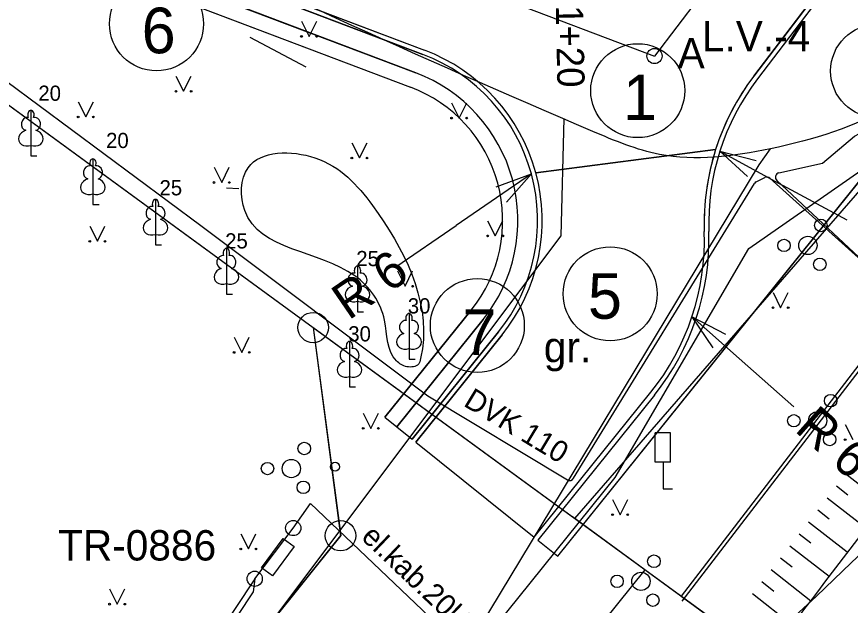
# Model space of a CAD drawing. Extents: x 514086 to 514457, y 297399 to 297567.
# Drawn here: x 514219.51 to 514246.93, y 297411.35 to 297430.72 of the extents above; entities that cross this region are included whole.
import ezdxf

# ---------------------------------------------------------------- set-up
doc = ezdxf.new("R2010")
doc.units = 0
for name, color, linetype in [('AA_Apzimejumi', 7, 'Continuous'), ('AA_Brauktuve', 7, 'Continuous'), ('AA_cela_mala', 7, 'Continuous'), ('AA_grants', 7, 'Continuous'), ('AA_Ielas_ass', 7, 'Continuous'), ('AA_izmeri', 7, 'Continuous'), ('AA_Nomale', 7, 'Continuous'), ('AA_Zale', 7, 'Continuous'), ('Level 1', 7, 'Continuous'), ('Level 14', 7, 'Continuous'), ('Level 16', 7, 'Continuous'), ('Level 18', 7, 'Continuous'), ('Level 23', 7, 'Continuous'), ('Level 29', 7, 'Continuous'), ('Level 31', 7, 'Continuous'), ('Level 32', 7, 'Continuous'), ('Level 35', 7, 'Continuous'), ('Level 36', 7, 'Continuous'), ('Level 37', 7, 'Continuous'), ('Level 42', 7, 'Continuous'), ('Level 45', 7, 'Continuous'), ('Level 46', 7, 'Continuous'), ('Level 61', 7, 'Continuous'), ('Level 7', 7, 'Continuous')]:
    doc.layers.add(name, color=color, linetype=linetype)

msp = doc.modelspace()

# ---------------------------------------------------------------- linework, layer by layer
at = {"layer": 'AA_Apzimejumi'}
for centre in [(514224.106, 297430.487), (514247.83, 297428.935), (514239.938, 297428.287), (514239.03, 297421.6), (514234.661, 297420.557)]:
    msp.add_circle(centre, 1.546, dxfattribs=at)
at = {"layer": 'AA_Brauktuve'}
msp.add_line((514236.585, 297425.586), (514242.499, 297426.346), dxfattribs=at)
for points in [[(514211.866, 297437.597), (514214.554, 297436.578), (514232.921, 297429.621)], [(514243.754, 297428.764), (514246.598, 297432.504)], [(514236.585, 297425.586), (514242.499, 297426.346)]]:
    msp.add_lwpolyline(points, dxfattribs=at)
for centre, radius, start, end in [((514230.796, 297424.01), 6, 15.2367, 69.2528), ((514250.123, 297423.922), 8, 142.7529, 162.3604)]:
    msp.add_arc(centre, radius, start, end, dxfattribs=at)
at = {"layer": 'AA_cela_mala'}
for p, q in [((514214.501, 297436.438), (514232.868, 297429.48)), ((514214.554, 297436.578), (514232.921, 297429.621)), ((514246.598, 297432.504), (514243.754, 297428.764)), ((514246.718, 297432.413), (514243.874, 297428.673)), ((514235.356, 297420.346), (514232.52, 297416.815)), ((514232.637, 297416.721), (514235.473, 297420.252)), ((514236.535, 297413.59), (514240.369, 297418.362)), ((514240.486, 297418.268), (514236.652, 297413.496)), ((514232.637, 297416.721), (514236.535, 297413.59))]:
    msp.add_line(p, q, dxfattribs=at)
for centre, radius, start, end in [((514230.796, 297424.01), 5.85, 321.2206, 69.2528), ((514230.796, 297424.01), 6, 321.2206, 69.2528), ((514250.123, 297423.922), 8, 142.7529, 181.9678), ((514250.123, 297423.922), 7.85, 142.7529, 181.9678), ((514234.132, 297423.372), 8, 321.2208, 1.9678), ((514234.132, 297423.372), 8.15, 321.2208, 1.9678)]:
    msp.add_arc(centre, radius, start, end, dxfattribs=at)
at = {"layer": 'AA_grants'}
for points in [[(514242.499, 297426.346), (514236.585, 297425.586)], [(514235.473, 297420.252), (514232.637, 297416.721), (514236.535, 297413.59), (514240.369, 297418.362)]]:
    msp.add_lwpolyline(points, dxfattribs=at)
for centre, radius, start, end in [((514250.123, 297423.922), 8, 162.3604, 181.9678), ((514230.796, 297424.01), 6, 321.2206, 15.2367), ((514234.132, 297423.372), 8, 321.2208, 1.9678)]:
    msp.add_arc(centre, radius, start, end, dxfattribs=at)
at = {"layer": 'AA_Ielas_ass'}
for p in [(514245.01, 297435.371), (514233.507, 297432.072)]:
    msp.add_line(p, (514240.49, 297429.427), dxfattribs=at)
msp.add_circle((514240.49, 297429.427), 0.25, dxfattribs=at)
at = {"layer": 'AA_izmeri'}
for p, q in [((514242.642, 297426.301), (514244.715, 297425.17)), ((514236.44, 297425.547), (514233.96, 297423.85)), ((514246.822, 297424.02), (514244.715, 297425.17)), ((514231.979, 297422.494), (514233.96, 297423.85)), ((514241.723, 297420.846), (514243.277, 297419.471)), ((514245.075, 297417.881), (514243.277, 297419.471))]:
    msp.add_line(p, q, dxfattribs=at)
for points in [[(514243.552, 297425.462), (514242.642, 297426.301), (514243.839, 297425.989)], [(514235.28, 297425.117), (514236.44, 297425.547), (514235.619, 297424.622)], [(514242.423, 297419.827), (514241.723, 297420.846), (514242.82, 297420.276)]]:
    msp.add_lwpolyline(points, dxfattribs=at)
at = {"layer": 'AA_Nomale'}
for points in [[(514213.882, 297436.432), (514214.457, 297435.759), (514232.638, 297428.872)], [(514232.868, 297429.48), (514214.501, 297436.438)], [(514234.85, 297420.753), (514232.013, 297417.222), (514232.52, 297416.815), (514235.356, 297420.346)]]:
    msp.add_lwpolyline(points, dxfattribs=at)
for radius in [5.85, 5.2]:
    msp.add_arc((514230.796, 297424.01), radius, 321.2206, 69.2528, dxfattribs=at)
at = {"layer": 'AA_Zale'}
for p, q in [((514214.457, 297435.759), (514232.638, 297428.872)), ((514213.813, 297435.469), (514232.461, 297428.405)), ((514237.314, 297412.963), (514250.581, 297429.476)), ((514231.623, 297417.536), (514234.46, 297421.066)), ((514232.013, 297417.222), (514234.85, 297420.753)), ((514231.623, 297417.536), (514232.013, 297417.222)), ((514232.013, 297417.222), (514232.52, 297416.815)), ((514236.652, 297413.496), (514237.314, 297412.963))]:
    msp.add_line(p, q, dxfattribs=at)
for points in [[(514236.652, 297413.496), (514237.314, 297412.963), (514250.581, 297429.476), (514253.4, 297427.333), (514283.198, 297466.177), (514325.029, 297520.708), (514327.112, 297523.423), (514336.853, 297525.444), (514334.256, 297529.664)], [(514232.638, 297428.872), (514214.457, 297435.759), (514213.813, 297435.469), (514232.461, 297428.405)], [(514246.718, 297432.413), (514243.874, 297428.673)], [(514234.46, 297421.066), (514231.623, 297417.536)], [(514231.623, 297417.536), (514232.013, 297417.222), (514234.85, 297420.753)], [(514240.486, 297418.268), (514236.652, 297413.496)]]:
    msp.add_lwpolyline(points, dxfattribs=at)
for centre, radius, start, end in [((514230.796, 297424.01), 5.2, 321.2206, 69.2528), ((514230.796, 297424.01), 5.2, 321.2206, 69.2528), ((514250.123, 297423.922), 7.85, 142.7529, 181.9678), ((514230.796, 297424.01), 4.7, 321.2206, 69.2528), ((514230.796, 297424.01), 4.7, 321.2206, 69.2528), ((514234.132, 297423.372), 8.15, 321.2208, 1.9678)]:
    msp.add_arc(centre, radius, start, end, dxfattribs=at)
at = {"layer": 'Level 1'}
for p, q in [((514219.975, 297426.486), (514219.975, 297426.139)), ((514219.975, 297426.139), (514220.175, 297426.139)), ((514222.015, 297424.888), (514222.015, 297424.541)), ((514222.015, 297424.541), (514222.215, 297424.541)), ((514224.074, 297423.557), (514224.074, 297423.21)), ((514224.074, 297423.21), (514224.274, 297423.21)), ((514226.405, 297421.94), (514226.405, 297421.593)), ((514226.405, 297421.593), (514226.605, 297421.593)), ((514230.718, 297421.359), (514230.718, 297421.012)), ((514230.718, 297421.012), (514230.918, 297421.012)), ((514232.413, 297419.802), (514232.413, 297419.455)), ((514232.413, 297419.455), (514232.613, 297419.455)), ((514230.455, 297418.882), (514230.455, 297418.535)), ((514230.455, 297418.535), (514230.655, 297418.535))]:
    msp.add_line(p, q, dxfattribs=at)
for points in [[(514219.975, 297427.639), (514219.975, 297426.486)], [(514220.064, 297427.407), (514220.063, 297427.408)], [(514222.015, 297426.041), (514222.015, 297424.888)], [(514222.105, 297425.809), (514222.104, 297425.81)], [(514224.074, 297424.71), (514224.074, 297423.557)], [(514224.163, 297424.477), (514224.162, 297424.478)], [(514226.405, 297423.093), (514226.405, 297421.94)], [(514226.495, 297422.861), (514226.494, 297422.862)], [(514230.718, 297422.512), (514230.718, 297421.359)], [(514230.808, 297422.28), (514230.807, 297422.281)], [(514232.413, 297420.955), (514232.413, 297419.802)], [(514232.503, 297420.723), (514232.502, 297420.724)], [(514230.455, 297420.035), (514230.455, 297418.882)], [(514230.545, 297419.803), (514230.544, 297419.804)]]:
    msp.add_lwpolyline(points, dxfattribs=at)
for centre, radius in [((514245.961, 297423.853), 0.207), ((514245.534, 297423.193), 0.301), ((514244.75, 297423.193), 0.204), ((514245.929, 297422.573), 0.205), ((514246.284, 297418.084), 0.207), ((514245.857, 297417.424), 0.301), ((514245.073, 297417.424), 0.204), ((514246.252, 297416.804), 0.205), ((514228.968, 297416.51), 0.207), ((514227.757, 297415.85), 0.204), ((514228.541, 297415.85), 0.301), ((514228.936, 297415.23), 0.205), ((514240.469, 297412.799), 0.207), ((514239.258, 297412.139), 0.204), ((514240.042, 297412.139), 0.301), ((514240.437, 297411.519), 0.205)]:
    msp.add_circle(centre, radius, dxfattribs=at)
for centre, major_axis, ratio, start_param, end_param in [((514219.975, 297427.489), (0, -0.15), 0.707107, 3.14537, 5.287485), ((514219.974, 297427.489), (0, -0.15), 0.707107, 0.995701, 3.137816), ((514219.846, 297427.194), (-0.039, -0.212), 0.861323, 3.141593, 6.283185), ((514220.103, 297427.194), (0.039, -0.212), 0.861323, 0, 3.141593), ((514219.885, 297426.732), (0.307, 0.095), 0.814445, 1.570796, 4.752015), ((514220.064, 297426.732), (-0.307, 0.095), 0.814445, 1.531171, 4.712389), ((514222.016, 297425.891), (0, -0.15), 0.707107, 3.14537, 5.287485), ((514222.015, 297425.891), (0, -0.15), 0.707107, 0.995701, 3.137816), ((514221.887, 297425.597), (-0.039, -0.212), 0.861323, 3.141593, 6.283185), ((514222.144, 297425.597), (0.039, -0.212), 0.861323, 0, 3.141593), ((514221.926, 297425.134), (0.307, 0.095), 0.814445, 1.570796, 4.752015), ((514222.105, 297425.134), (-0.307, 0.095), 0.814445, 1.531171, 4.712389), ((514224.074, 297424.56), (0, -0.15), 0.707107, 3.14537, 5.287485), ((514224.073, 297424.56), (0, -0.15), 0.707107, 0.995701, 3.137816), ((514223.945, 297424.265), (-0.039, -0.212), 0.861323, 3.141593, 6.283185), ((514224.202, 297424.265), (0.039, -0.212), 0.861323, 0, 3.141593), ((514223.984, 297423.803), (0.307, 0.095), 0.814445, 1.570796, 4.752015), ((514224.163, 297423.803), (-0.307, 0.095), 0.814445, 1.531171, 4.712389), ((514226.277, 297422.648), (-0.039, -0.212), 0.861323, 3.141593, 6.283185), ((514226.405, 297422.943), (0, -0.15), 0.707107, 3.14537, 5.287485), ((514226.405, 297422.943), (0, -0.15), 0.707107, 0.995701, 3.137816), ((514226.533, 297422.648), (0.039, -0.212), 0.861323, 0, 3.141593), ((514226.315, 297422.186), (0.307, 0.095), 0.814445, 1.570796, 4.752015), ((514226.495, 297422.186), (-0.307, 0.095), 0.814445, 1.531171, 4.712389), ((514230.718, 297422.362), (0, -0.15), 0.707107, 3.14537, 5.287485), ((514230.718, 297422.362), (0, -0.15), 0.707107, 0.995701, 3.137816), ((514230.59, 297422.067), (-0.039, -0.212), 0.861323, 3.141593, 6.283185), ((514230.846, 297422.067), (0.039, -0.212), 0.861323, 0, 3.141593), ((514230.628, 297421.605), (0.307, 0.095), 0.814445, 1.570796, 4.752015), ((514230.808, 297421.605), (-0.307, 0.095), 0.814445, 1.531171, 4.712389), ((514232.413, 297420.805), (0, -0.15), 0.707107, 3.14537, 5.287485), ((514232.413, 297420.805), (0, -0.15), 0.707107, 0.995701, 3.137816), ((514232.285, 297420.51), (-0.039, -0.212), 0.861323, 3.141593, 6.283185), ((514232.541, 297420.51), (0.039, -0.212), 0.861323, 0, 3.141593), ((514232.323, 297420.048), (0.307, 0.095), 0.814445, 1.570796, 4.752015), ((514232.503, 297420.048), (-0.307, 0.095), 0.814445, 1.531171, 4.712389), ((514230.455, 297419.885), (0, -0.15), 0.707107, 3.14537, 5.287485), ((514230.455, 297419.885), (0, -0.15), 0.707107, 0.995701, 3.137816), ((514230.327, 297419.59), (-0.039, -0.212), 0.861323, 3.141593, 6.283185), ((514230.583, 297419.59), (0.039, -0.212), 0.861323, 0, 3.141593), ((514230.365, 297419.128), (0.307, 0.095), 0.814445, 1.570796, 4.752015), ((514230.545, 297419.128), (-0.307, 0.095), 0.814445, 1.531171, 4.712389)]:
    msp.add_ellipse(centre, major_axis=major_axis, ratio=ratio, start_param=start_param, end_param=end_param, dxfattribs=at)
at = {"layer": 'Level 14'}
msp.add_circle((514229.982, 297415.908), 0.148, dxfattribs=at)
at = {"layer": 'Level 16'}
for p, q in [((514241.016, 297417.027), (514240.516, 297417.027)), ((514240.516, 297416.058), (514240.516, 297417.027)), ((514241.016, 297416.058), (514241.016, 297417.027)), ((514241.016, 297416.058), (514240.516, 297416.058)), ((514240.77, 297416.058), (514240.77, 297415.18)), ((514240.77, 297415.18), (514241.085, 297415.18))]:
    msp.add_line(p, q, dxfattribs=at)
at = {"layer": 'Level 18'}
msp.add_line((514227.337, 297412.224), (514228.605, 297413.892), dxfattribs=at)
msp.add_lwpolyline([(514227.561, 297412.586), (514228.272, 297413.553), (514228.635, 297413.286), (514227.924, 297412.319)], close=True, dxfattribs=at)
for centre in [(514228.605, 297413.892), (514227.337, 297412.224)]:
    msp.add_circle(centre, 0.25, dxfattribs=at)
at = {"layer": 'Level 23'}
for p, q in [((514228.877, 297430.571), (514229.127, 297430.071)), ((514229.127, 297430.071), (514229.377, 297430.571)), ((514224.747, 297428.766), (514224.997, 297428.266)), ((514224.997, 297428.266), (514225.247, 297428.766)), ((514221.53, 297427.922), (514221.78, 297427.422)), ((514221.78, 297427.422), (514222.03, 297427.922)), ((514233.812, 297427.883), (514234.062, 297427.383)), ((514234.062, 297427.383), (514234.312, 297427.883)), ((514230.533, 297426.571), (514230.783, 297426.071)), ((514230.783, 297426.071), (514231.033, 297426.571)), ((514226.001, 297425.765), (514226.251, 297425.265)), ((514226.251, 297425.265), (514226.501, 297425.765)), ((514234.999, 297424.008), (514235.249, 297423.508)), ((514235.249, 297423.508), (514235.499, 297424.008)), ((514221.912, 297423.829), (514222.162, 297423.329)), ((514222.162, 297423.329), (514222.412, 297423.829)), ((514232.032, 297422.352), (514232.282, 297421.852)), ((514232.282, 297421.852), (514232.532, 297422.352)), ((514244.388, 297421.645), (514244.638, 297421.145)), ((514244.638, 297421.145), (514244.888, 297421.645)), ((514226.66, 297420.172), (514226.91, 297419.672)), ((514226.91, 297419.672), (514227.16, 297420.172)), ((514230.908, 297417.672), (514231.158, 297417.172)), ((514231.158, 297417.172), (514231.408, 297417.672)), ((514246.762, 297417.301), (514247.012, 297416.801)), ((514239.11, 297414.832), (514239.36, 297414.332)), ((514239.36, 297414.332), (514239.61, 297414.832)), ((514226.878, 297413.703), (514227.128, 297413.203)), ((514227.128, 297413.203), (514227.378, 297413.703)), ((514222.563, 297411.887), (514222.813, 297411.387)), ((514222.813, 297411.387), (514223.063, 297411.887))]:
    msp.add_line(p, q, dxfattribs=at)
for centre, radius in [((514228.877, 297430.071), 0.028), ((514229.377, 297430.071), 0.0263), ((514224.746, 297428.266), 0.028), ((514225.246, 297428.266), 0.0263), ((514221.529, 297427.422), 0.028), ((514222.029, 297427.422), 0.0263), ((514233.812, 297427.383), 0.028), ((514234.312, 297427.383), 0.0263), ((514230.532, 297426.07), 0.028), ((514231.032, 297426.07), 0.0263), ((514226, 297425.265), 0.028), ((514226.5, 297425.265), 0.0263), ((514234.999, 297423.508), 0.028), ((514235.499, 297423.508), 0.0263), ((514221.912, 297423.328), 0.028), ((514222.412, 297423.328), 0.0263), ((514232.032, 297421.851), 0.028), ((514232.532, 297421.851), 0.0263), ((514244.388, 297421.145), 0.028), ((514244.888, 297421.145), 0.0263), ((514226.66, 297419.672), 0.028), ((514227.16, 297419.672), 0.0263), ((514230.907, 297417.172), 0.028), ((514231.407, 297417.172), 0.0263), ((514246.762, 297416.801), 0.028), ((514239.109, 297414.332), 0.028), ((514239.609, 297414.332), 0.0263), ((514226.878, 297413.203), 0.028), ((514227.378, 297413.203), 0.0263), ((514222.563, 297411.387), 0.028), ((514223.063, 297411.387), 0.0263)]:
    msp.add_circle(centre, radius, dxfattribs=at)
at = {"layer": 'Level 29'}
for p, q in [((514325.029, 297520.708), (514241.366, 297411.646)), ((514139.134, 297486.37), (514229.261, 297420.493)), ((514229.248, 297420.503), (514241.354, 297411.656)), ((514229.261, 297420.493), (514230.166, 297413.646)), ((514220.185, 297401.223), (514230.166, 297413.646)), ((514241.366, 297411.646), (514242.591, 297410.75))]:
    msp.add_line(p, q, dxfattribs=at)
at = {"layer": 'Level 31'}
for p, q in [((514246.779, 297415.68), (514248.041, 297414.698)), ((514246.472, 297415.285), (514246.851, 297414.99)), ((514246.165, 297414.891), (514247.43, 297413.906)), ((514245.857, 297414.496), (514246.239, 297414.199)), ((514245.55, 297414.101), (514246.83, 297413.106)), ((514245.243, 297413.707), (514245.629, 297413.406)), ((514244.936, 297413.312), (514246.23, 297412.306)), ((514244.629, 297412.917), (514245.02, 297412.613)), ((514244.322, 297412.523), (514245.635, 297411.502)), ((514244.015, 297412.128), (514244.412, 297411.819)), ((514243.708, 297411.733), (514245.041, 297410.697))]:
    msp.add_line(p, q, dxfattribs=at)
msp.add_spline([(514238.182, 297404.63), (514268.566, 297443.685), (514271.22, 297450.146), (514276.219, 297454.734), (514284.527, 297466.568), (514290.967, 297471.565), (514316.058, 297506.3)], degree=3, dxfattribs=at)
at = {"layer": 'Level 32'}
msp.add_line((514226.811, 297425.06), (514226.412, 297425.083), dxfattribs=at)
msp.add_spline([(514232.773, 297419.368), (514232.852, 297419.791), (514231.214, 297424.503), (514229.318, 297426.076), (514227.122, 297425.752), (514227.007, 297424.341), (514230.636, 297422.19), (514231.607, 297420.733), (514232, 297419.391), (514232.341, 297419.202), (514232.56, 297419.202), (514232.72, 297419.277), (514232.773, 297419.368)], degree=3, dxfattribs=at)
at = {"layer": 'Level 35'}
msp.add_line((514255.58, 297429.98), (514241.388, 297411.486), dxfattribs=at)
at = {"layer": 'Level 36'}
msp.add_spline([(514320.804, 297502.52), (514306.724, 297488.103), (514301.133, 297479.973), (514270.315, 297441.123), (514246.087, 297412.115), (514239.566, 297403.275)], degree=3, dxfattribs=at)
at = {"layer": 'Level 37'}
msp.add_line((514243.929, 297425.848), (514244.303, 297426.375), dxfattribs=at)
for points in [[(514237.507, 297427.371), (514237.405, 297423.511), (514227.557, 297410.382), (514220.597, 297401.223)], [(514228.516, 297401.223), (514234.052, 297409.474), (514243.929, 297425.848)]]:
    msp.add_lwpolyline(points, dxfattribs=at)
msp.add_spline([(514253.266, 297433.337), (514251.138, 297430.251), (514248.312, 297427.806), (514244.303, 297426.375), (514240.654, 297426.189), (514238.461, 297426.944), (514221.666, 297434.465), (514216.865, 297436.605), (514214.873, 297437.26), (514213.856, 297437.22), (514212.841, 297436.761), (514210.686, 297435.157)], degree=3, dxfattribs=at)
at = {"layer": 'Level 42'}
msp.add_line((514227.181, 297430.044), (514229.017, 297429.067), dxfattribs=at)
at = {"layer": 'Level 45'}
msp.add_line((514233.037, 297418.247), (514237.623, 297415.479), dxfattribs=at)
for points in [[(514244.583, 297425.582), (514246.018, 297425.897), (514247.064, 297426.784), (514250.354, 297428.549), (514251.967, 297430.455), (514256.157, 297436.259), (514261.4, 297444.303), (514263.602, 297446.189), (514265.306, 297447.481)], [(514213.849, 297432.553), (514225.562, 297423.85), (514233.037, 297418.247), (514237.623, 297415.479)], [(514243.835, 297425.283), (514244.115, 297425.425)], [(514244.283, 297425.403), (514248.057, 297422.015), (514244.513, 297425.326)], [(514237.829, 297415.529), (514243.775, 297425.228)]]:
    msp.add_lwpolyline(points, dxfattribs=at)
for centre, start, end in [((514244.183, 297425.292), 48.0793, 116.8806), ((514244.615, 297425.436), 102.373, 226.9487), ((514243.903, 297425.149), 116.8806, 148.4892), ((514237.701, 297415.607), 238.8881, 328.4892)]:
    msp.add_arc(centre, 0.15, start, end, dxfattribs=at)
at = {"layer": 'Level 46'}
for p, q in [((514229.26, 297420.49), (514230.16, 297413.64)), ((514230.16, 297413.64), (514220.185, 297401.223))]:
    msp.add_line(p, q, dxfattribs=at)
msp.add_lwpolyline([(514139.134, 297486.37), (514229.261, 297420.493), (514237.863, 297414.208), (514250.009, 297428.181), (514295.433, 297494.723), (514312.775, 297524.542), (514316.491, 297528.738), (514320.446, 297531.016), (514328.236, 297532.215), (514332.539, 297530.572), (514332.631, 297530.536), (514341.642, 297542.18), (514320.211, 297553.997), (514285.885, 297496.27), (514243.195, 297433.696), (514241.534, 297432.407), (514239.451, 297432.203), (514209.969, 297445.237), (514194.45, 297457.413), (514175.859, 297473.677), (514139.316, 297503.122), (514133.046, 297508.174), (514130.604, 297489.221)], close=True, dxfattribs=at)
for points in [[(514229.261, 297420.493), (514230.166, 297413.646), (514220.185, 297401.223)], [(514240.166, 297412.522), (514237.788, 297414.26)], [(514234.937, 297401.223), (514242.591, 297410.75), (514240.166, 297412.522), (514231.088, 297401.223)]]:
    msp.add_lwpolyline(points, dxfattribs=at)
for centre in [(514229.26, 297420.49), (514230.16, 297413.64)]:
    msp.add_circle(centre, 0.5, dxfattribs=at)
at = {"layer": 'Level 61'}
msp.add_lwpolyline([(514228.605, 297413.892), (514229.168, 297414.699), (514234.462, 297409.66), (514239.192, 297415.557), (514243.591, 297423.09), (514250.856, 297428.146), (514250.871, 297429.329), (514257.62, 297437.772), (514268.028, 297450.791), (514271.687, 297455.368), (514283.043, 297472.127), (514296.63, 297489.788), (514299.744, 297491.72), (514308.223, 297503.049), (514310.505, 297506.097), (514314.057, 297510.598), (514322.921, 297521.831), (514325.028, 297524.077), (514326.601, 297524.074), (514327.377, 297523.947), (514343.661, 297512.323), (514343.876, 297512.066)], dxfattribs=at)
at = {"layer": 'Level 7'}
for points in [[(514227.337, 297412.224), (514220.053, 297401.223)], [(514227.337, 297412.224), (514227.292, 297411.794), (514220.292, 297401.223)]]:
    msp.add_lwpolyline(points, dxfattribs=at)

# ---------------------------------------------------------------- texts
at = {"layer": 'AA_Apzimejumi'}
for s, p in [('6', (514223.62, 297429.518)), ('1', (514239.452, 297427.318)), ('5', (514238.301, 297420.779)), ('7', (514234.175, 297419.588))]:
    msp.add_text(s, height=1.5, dxfattribs=at).set_placement(p)
at = {"layer": 'AA_Ielas_ass'}
for s, height, rotation, p in [(' 1+20', 0.9, 271.1307, (514237.235, 297431.426)), ('L.V.-4', 1, 360, (514242.048, 297429.584))]:
    msp.add_text(s, height=height, rotation=rotation, dxfattribs=at).set_placement(p)
at = {"layer": 'AA_izmeri'}
for rotation, p in [(34.3868, (514230.425, 297420.713)), (318.5074, (514245.066, 297417.098))]:
    msp.add_text('R 6', height=1.2, rotation=rotation, dxfattribs=at).set_placement(p)
at = {"layer": 'Level 1'}
for s, p in [('20', (514220.22, 297427.953)), ('20', (514222.448, 297426.399)), (' 25', (514224.02, 297424.842)), (' 25', (514226.18, 297423.093)), (' 25', (514230.493, 297422.512)), (' 30', (514232.188, 297420.955)), (' 30', (514230.23, 297420.035))]:
    msp.add_text(s, height=0.5, dxfattribs=at).set_placement(p)
at = {"layer": 'Level 18'}
msp.add_text('TR-0886', height=1, dxfattribs=at).set_placement((514220.867, 297412.824))
at = {"layer": 'Level 37'}
for s, p in [('A', (514241.25, 297429.023)), ('gr.', (514236.848, 297419.348))]:
    msp.add_text(s, height=1, dxfattribs=at).set_placement(p)
at = {"layer": 'Level 45'}
msp.add_text('DVK 110', height=0.7, rotation=328.8881, dxfattribs=at).set_placement((514234.172, 297417.933))
at = {"layer": 'Level 61'}
msp.add_text('el.kab.20kV', height=0.7, rotation=316.4147, dxfattribs=at).set_placement((514230.807, 297413.553))

doc.saveas('drawing.dxf')
